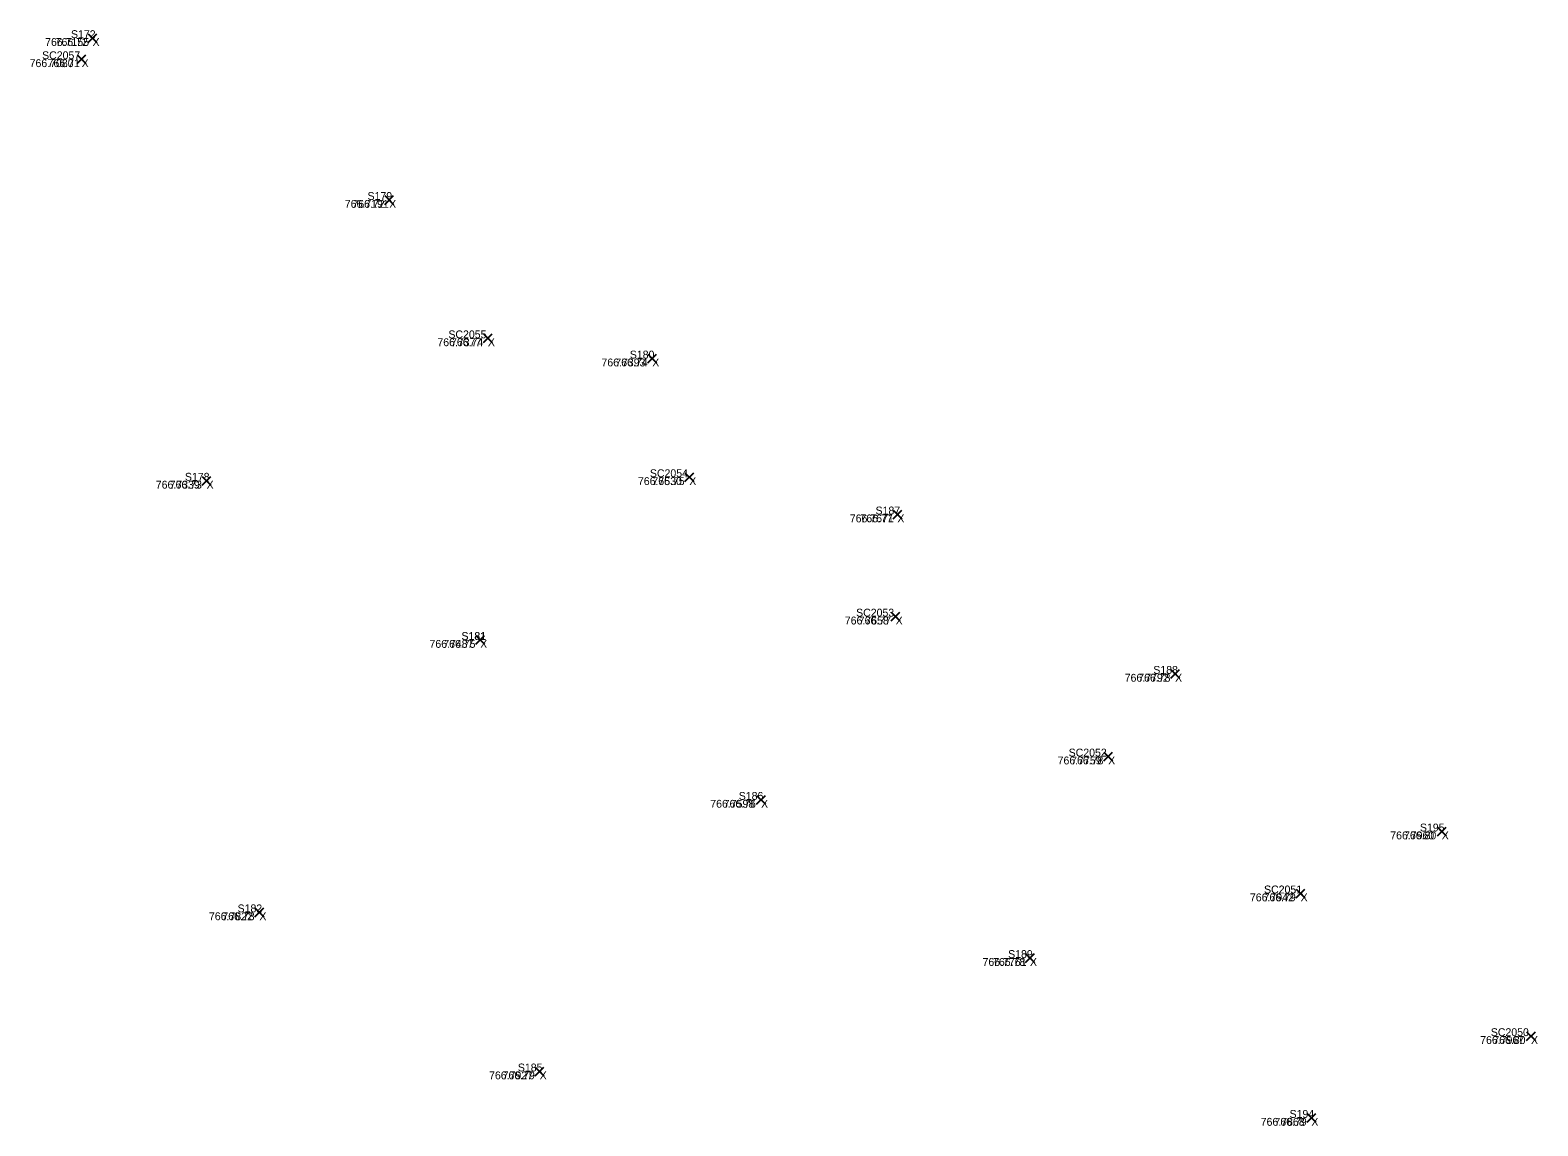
# Model space of a CAD drawing. Extents: x 1845019 to 1877956, y 680444 to 701081.
# Drawn here: x 1857603.32 to 1857614.81, y 694329.1 to 694337.45 of the extents above; entities that cross this region are included whole.
import ezdxf

# ---------------------------------------------------------------- set-up
doc = ezdxf.new("R2010")
doc.units = 0
for name, color, linetype in [('SV_X_Random_Point', 7, 'Continuous'), ('SV_X_Text_Comment', 7, 'Continuous'), ('SV_X_Text_Elevation', 7, 'Continuous'), ('SV_X_Text_Name', 7, 'Continuous')]:
    doc.layers.add(name, color=color, linetype=linetype)

msp = doc.modelspace()

# ---------------------------------------------------------------- linework, layer by layer
at = {"layer": 'SV_X_Random_Point'}
for p, q in [((1857603.766, 694337.354), (1857603.832, 694337.421)), ((1857603.766, 694337.421), (1857603.832, 694337.354)), ((1857603.766, 694337.354), (1857603.832, 694337.421)), ((1857603.766, 694337.421), (1857603.832, 694337.354)), ((1857603.682, 694337.194), (1857603.749, 694337.261)), ((1857603.682, 694337.261), (1857603.749, 694337.194)), ((1857603.682, 694337.194), (1857603.749, 694337.261)), ((1857603.682, 694337.261), (1857603.749, 694337.194)), ((1857606.026, 694336.121), (1857606.093, 694336.188)), ((1857606.026, 694336.188), (1857606.093, 694336.121)), ((1857606.026, 694336.121), (1857606.093, 694336.188)), ((1857606.026, 694336.188), (1857606.093, 694336.121)), ((1857606.777, 694335.068), (1857606.844, 694335.134)), ((1857606.777, 694335.134), (1857606.844, 694335.068)), ((1857606.777, 694335.068), (1857606.844, 694335.134)), ((1857606.777, 694335.134), (1857606.844, 694335.068)), ((1857608.03, 694334.913), (1857608.096, 694334.98)), ((1857608.03, 694334.98), (1857608.096, 694334.913)), ((1857608.03, 694334.913), (1857608.096, 694334.98)), ((1857608.03, 694334.98), (1857608.096, 694334.913)), ((1857604.635, 694333.982), (1857604.701, 694334.049)), ((1857604.635, 694334.049), (1857604.701, 694333.982)), ((1857604.635, 694333.982), (1857604.701, 694334.049)), ((1857604.635, 694334.049), (1857604.701, 694333.982)), ((1857608.312, 694334.009), (1857608.379, 694334.076)), ((1857608.312, 694334.076), (1857608.379, 694334.009)), ((1857608.312, 694334.009), (1857608.379, 694334.076)), ((1857608.312, 694334.076), (1857608.379, 694334.009)), ((1857609.897, 694333.725), (1857609.963, 694333.792)), ((1857609.897, 694333.792), (1857609.963, 694333.725)), ((1857609.897, 694333.725), (1857609.963, 694333.792)), ((1857609.897, 694333.792), (1857609.963, 694333.725)), ((1857609.883, 694332.948), (1857609.95, 694333.015)), ((1857609.883, 694333.015), (1857609.95, 694332.948)), ((1857609.883, 694332.948), (1857609.95, 694333.015)), ((1857609.883, 694333.015), (1857609.95, 694332.948)), ((1857606.719, 694332.77), (1857606.785, 694332.837)), ((1857606.719, 694332.837), (1857606.785, 694332.77)), ((1857606.719, 694332.77), (1857606.785, 694332.837)), ((1857606.719, 694332.837), (1857606.785, 694332.77)), ((1857612.013, 694332.511), (1857612.08, 694332.578)), ((1857612.013, 694332.578), (1857612.08, 694332.511)), ((1857612.013, 694332.511), (1857612.08, 694332.578)), ((1857612.013, 694332.578), (1857612.08, 694332.511)), ((1857611.502, 694331.881), (1857611.569, 694331.948)), ((1857611.502, 694331.948), (1857611.569, 694331.881)), ((1857611.502, 694331.881), (1857611.569, 694331.948)), ((1857611.502, 694331.948), (1857611.569, 694331.881)), ((1857608.858, 694331.551), (1857608.925, 694331.618)), ((1857608.858, 694331.618), (1857608.925, 694331.551)), ((1857608.858, 694331.551), (1857608.925, 694331.618)), ((1857608.858, 694331.618), (1857608.925, 694331.551)), ((1857614.044, 694331.31), (1857614.111, 694331.377)), ((1857614.044, 694331.377), (1857614.111, 694331.31)), ((1857614.044, 694331.31), (1857614.111, 694331.377)), ((1857614.044, 694331.377), (1857614.111, 694331.31)), ((1857612.968, 694330.838), (1857613.035, 694330.905)), ((1857612.968, 694330.905), (1857613.035, 694330.838)), ((1857612.968, 694330.838), (1857613.035, 694330.905)), ((1857612.968, 694330.905), (1857613.035, 694330.838)), ((1857605.036, 694330.695), (1857605.103, 694330.762)), ((1857605.036, 694330.762), (1857605.103, 694330.695)), ((1857605.036, 694330.695), (1857605.103, 694330.762)), ((1857605.036, 694330.762), (1857605.103, 694330.695)), ((1857610.907, 694330.347), (1857610.974, 694330.414)), ((1857610.907, 694330.414), (1857610.974, 694330.347)), ((1857610.907, 694330.347), (1857610.974, 694330.414)), ((1857610.907, 694330.414), (1857610.974, 694330.347)), ((1857614.724, 694329.752), (1857614.791, 694329.818)), ((1857614.724, 694329.818), (1857614.791, 694329.752)), ((1857614.724, 694329.752), (1857614.791, 694329.818)), ((1857614.724, 694329.818), (1857614.791, 694329.752)), ((1857607.172, 694329.482), (1857607.238, 694329.549)), ((1857607.172, 694329.549), (1857607.238, 694329.482)), ((1857607.172, 694329.482), (1857607.238, 694329.549)), ((1857607.172, 694329.549), (1857607.238, 694329.482)), ((1857613.051, 694329.129), (1857613.118, 694329.196)), ((1857613.051, 694329.196), (1857613.118, 694329.129)), ((1857613.051, 694329.129), (1857613.118, 694329.196)), ((1857613.051, 694329.196), (1857613.118, 694329.129))]:
    msp.add_line(p, q, dxfattribs=at)

# ---------------------------------------------------------------- texts
at = {"layer": 'SV_X_Text_Comment'}
for p in [(1857603.799, 694337.328), (1857603.716, 694337.167), (1857606.059, 694336.095), (1857606.811, 694335.041), (1857608.063, 694334.887), (1857604.668, 694333.956), (1857608.345, 694333.983), (1857609.93, 694333.699), (1857609.917, 694332.921), (1857606.752, 694332.743), (1857612.046, 694332.485), (1857611.536, 694331.855), (1857608.892, 694331.525), (1857614.077, 694331.284), (1857613.002, 694330.812), (1857605.07, 694330.668), (1857610.94, 694330.32), (1857614.757, 694329.725), (1857607.205, 694329.456), (1857613.084, 694329.102)]:
    msp.add_text('X', height=0.06, dxfattribs=at).set_placement(p)
at = {"layer": 'SV_X_Text_Elevation'}
for s, p in [('766.7155', (1857603.438, 694337.328)), ('766.72', (1857603.518, 694337.328)), ('766.7080', (1857603.32, 694337.167)), ('766.71', (1857603.457, 694337.167)), ('766.7191', (1857605.721, 694336.095)), ('766.72', (1857605.779, 694336.095)), ('766.7377', (1857606.426, 694335.041)), ('766.74', (1857606.53, 694335.041)), ('766.7393', (1857607.676, 694334.887)), ('766.74', (1857607.782, 694334.887)), ('766.7339', (1857604.281, 694333.956)), ('766.73', (1857604.387, 694333.956)), ('766.7530', (1857607.954, 694333.983)), ('766.75', (1857608.064, 694333.983)), ('766.7671', (1857609.568, 694333.699)), ('766.77', (1857609.649, 694333.699)), ('766.7658', (1857609.53, 694332.921)), ('766.77', (1857609.636, 694332.921)), ('766.7487', (1857606.366, 694332.743)), ('766.75', (1857606.471, 694332.743)), ('766.7792', (1857611.662, 694332.485)), ('766.78', (1857611.765, 694332.485)), ('766.7759', (1857611.151, 694331.855)), ('766.78', (1857611.254, 694331.855)), ('766.7598', (1857608.505, 694331.525)), ('766.76', (1857608.607, 694331.525)), ('766.7960', (1857613.685, 694331.284)), ('766.80', (1857613.79, 694331.284)), ('766.7942', (1857612.616, 694330.812)), ('766.79', (1857612.72, 694330.812)), ('766.7822', (1857604.686, 694330.668)), ('766.78', (1857604.788, 694330.668)), ('766.7761', (1857610.579, 694330.32)), ('766.78', (1857610.659, 694330.32)), ('766.7967', (1857614.37, 694329.725)), ('766.80', (1857614.47, 694329.725)), ('766.7927', (1857606.82, 694329.456)), ('766.79', (1857606.923, 694329.456)), ('766.7868', (1857612.698, 694329.102)), ('766.79', (1857612.803, 694329.102))]:
    msp.add_text(s, height=0.06, dxfattribs=at).set_placement(p)
at = {"layer": 'SV_X_Text_Name'}
for s, p in [('S172', (1857603.635, 694337.388)), ('S172', (1857603.635, 694337.388)), ('SC2057', (1857603.415, 694337.227)), ('SC2057', (1857603.415, 694337.227)), ('S179', (1857605.894, 694336.155)), ('S179', (1857605.894, 694336.155)), ('SC2055', (1857606.51, 694335.101)), ('SC2055', (1857606.51, 694335.101)), ('S180', (1857607.892, 694334.947)), ('S180', (1857607.892, 694334.947)), ('SC2054', (1857608.045, 694334.043)), ('SC2054', (1857608.045, 694334.043)), ('S178', (1857604.503, 694334.016)), ('S178', (1857604.503, 694334.016)), ('S187', (1857609.764, 694333.759)), ('S187', (1857609.764, 694333.759)), ('SC2053', (1857609.616, 694332.981)), ('SC2053', (1857609.616, 694332.981)), ('S181', (1857606.609, 694332.803)), ('S181', (1857606.61, 694332.803)), ('S188', (1857611.88, 694332.545)), ('S188', (1857611.88, 694332.545)), ('SC2052', (1857611.235, 694331.915)), ('SC2052', (1857611.235, 694331.915)), ('S186', (1857608.722, 694331.585)), ('S186', (1857608.722, 694331.585)), ('S195', (1857613.911, 694331.344)), ('S195', (1857613.911, 694331.344)), ('SC2051', (1857612.723, 694330.872)), ('SC2051', (1857612.724, 694330.872)), ('S182', (1857604.904, 694330.728)), ('S182', (1857604.904, 694330.728)), ('S189', (1857610.774, 694330.38)), ('S189', (1857610.774, 694330.38)), ('SC2050', (1857614.451, 694329.785)), ('SC2050', (1857614.451, 694329.785)), ('S185', (1857607.039, 694329.516)), ('S185', (1857607.039, 694329.516)), ('S194', (1857612.918, 694329.162)), ('S194', (1857612.918, 694329.162))]:
    msp.add_text(s, height=0.06, dxfattribs=at).set_placement(p)

doc.saveas('drawing.dxf')
